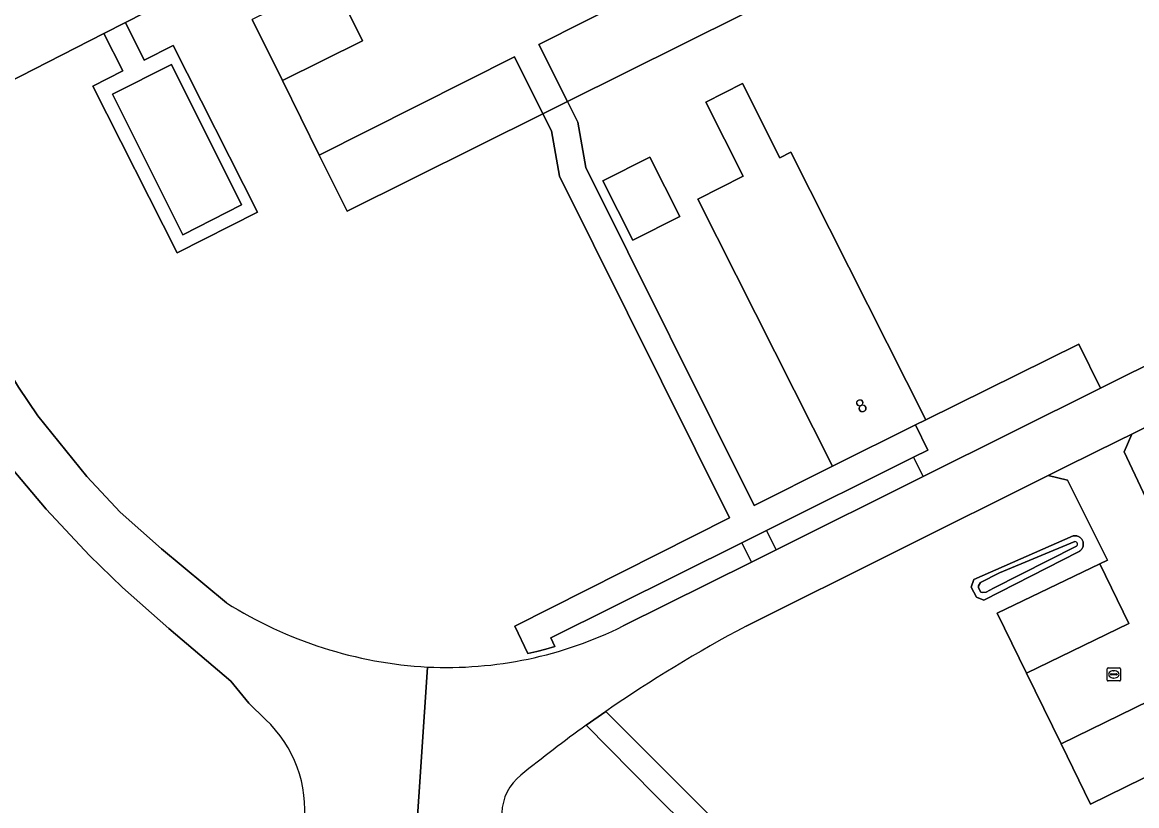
# Model space of a CAD drawing. Extents: x 158132 to 159664, y 385256 to 387218.
# Drawn here: x 159064.7 to 159149, y 386274.9 to 386334.2 of the extents above; entities that cross this region are included whole.
import ezdxf

# ---------------------------------------------------------------- set-up
doc = ezdxf.new("R2010")
doc.units = 0
for name, color, linetype in [('IMGEO_Berm_groen', 7, 'Continuous'), ('IMGEO_Groenvoorziening', 7, 'Continuous'), ('IMGEO_Kolk', 7, 'Continuous'), ('IMGEO_Loofbos', 7, 'Continuous'), ('IMGEO_Oever', 7, 'Continuous'), ('IMGEO_Pand', 7, 'Continuous'), ('IMGEO_Pand_nummerreeks', 7, 'Continuous'), ('IMGEO_Parkeervlak_halfverhard', 7, 'Continuous'), ('IMGEO_Parkeervlak_open', 7, 'Continuous'), ('IMGEO_Rijbaan_lokaal_gesloten', 7, 'Continuous'), ('IMGEO_Rijbaan_lokaal_open', 7, 'Continuous'), ('IMGEO_Voetpad_open', 7, 'Continuous'), ('IMGEO_Waterloop', 7, 'Continuous')]:
    doc.layers.add(name, color=color, linetype=linetype)

msp = doc.modelspace()

# ---------------------------------------------------------------- linework, layer by layer
at = {"layer": 'IMGEO_Berm_groen'}
msp.add_lwpolyline([(159137.109, 386251.107), (159129.699, 386258.673), (159120.184, 386268.183), (159112.56, 386275.748), (159107.364, 386281.01)], dxfattribs=at)
for centre, radius, start, end in [((159167.991, 386196.497), 104.01, 125.6545, 129.08043), ((159104.761, 386274.249), 3.794, 128.06163, 228.1555)]:
    msp.add_arc(centre, radius, start, end, dxfattribs=at)
at = {"layer": 'IMGEO_Groenvoorziening'}
for points in [[(159158.608, 386354.428), (159105.953, 386328.242), (159106.738, 386326.663), (159107.337, 386323.246), (159120.07, 386297.644), (159126.002, 386300.637), (159115.808, 386320.841), (159119.244, 386322.574), (159116.412, 386328.188), (159119.201, 386329.595), (159122.033, 386323.981), (159122.863, 386324.4), (159133.085, 386304.138), (159144.653, 386309.856), (159146.313, 386306.52), (159187.744, 386327.14)], [(159085.768, 386341.008), (159072.465, 386334.219), (159073.901, 386331.373), (159076.083, 386332.475), (159082.461, 386319.846), (159076.384, 386316.777), (159070.007, 386329.407), (159072.281, 386330.555), (159070.847, 386333.393), (159061.295, 386328.518)], [(159119.874, 386293.362), (159119.145, 386294.827), (159104.695, 386287.635), (159104.996, 386286.96), (159104.313, 386286.771), (159103.626, 386286.599), (159102.935, 386286.444), (159101.95, 386288.501), (159118.21, 386296.706), (159105.338, 386322.589), (159104.739, 386326.006), (159104.088, 386327.315), (159089.251, 386319.936), (159087.154, 386324.178), (159084.365, 386329.818), (159082.079, 386334.443)], [(159186.019, 386321.678), (159148.667, 386303.059), (159148.09, 386301.717), (159150.98, 386295.609)], [(159057.062, 386320.945), (159063.133, 386308.664), (159064.373, 386306.618), (159065.843, 386304.447), (159069.55, 386299.848), (159072.072, 386297.131), (159075.195, 386294.366), (159080.133, 386290.273)], [(159108.848, 386282.056), (159117.567, 386273.343), (159130.648, 386260.403), (159140.343, 386250.704), (159148.101, 386242.94), (159161.049, 386260.864), (159173.188, 386277.68), (159184.907, 386293.934), (159196.39, 386309.759)], [(159166.651, 386285.382), (159145.544, 386275.043), (159143.317, 386279.598), (159140.694, 386284.963), (159138.479, 386289.495), (159146.258, 386293.231), (159146.826, 386293.504), (159143.804, 386299.576), (159142.345, 386299.908), (159119.464, 386288.503)], [(159110.158, 386288.526), (159119.874, 386293.362)]]:
    msp.add_lwpolyline(points, dxfattribs=at)
for points in [[(159114.449, 386319.54), (159110.896, 386317.747), (159108.63, 386322.237), (159112.184, 386324.031)], [(159132.873, 386299.831), (159132.148, 386301.298), (159121.01, 386295.755), (159121.739, 386294.29)], [(159144.636, 386294.139), (159137.467, 386290.481), (159136.925, 386290.7), (159136.523, 386291.463), (159136.707, 386292.056), (159144.244, 386295.351), (159144.3, 386295.359), (159144.356, 386295.362), (159144.412, 386295.36), (159144.468, 386295.354), (159144.523, 386295.342), (159144.576, 386295.326), (159144.628, 386295.305), (159144.678, 386295.279), (159144.726, 386295.249), (159144.771, 386295.215), (159144.812, 386295.178), (159144.851, 386295.137), (159144.885, 386295.093), (159144.916, 386295.045), (159144.942, 386294.996), (159144.964, 386294.944), (159144.981, 386294.891), (159144.994, 386294.836), (159145.001, 386294.78), (159145.004, 386294.724), (159145.002, 386294.668), (159144.995, 386294.612), (159144.983, 386294.558), (159144.967, 386294.504), (159144.946, 386294.452), (159144.92, 386294.402), (159144.89, 386294.355), (159144.856, 386294.31), (159144.818, 386294.268), (159144.777, 386294.23), (159144.733, 386294.196), (159144.686, 386294.165)]]:
    msp.add_lwpolyline(points, close=True, dxfattribs=at)
for centre, radius, start, end in [((159097.116, 386317.23), 31.861, 237.78851, 266.82735), ((159096.795, 386315.367), 29.983, 267.2441, 296.46767), ((159168.468, 386195.847), 104.817, 117.87331, 124.66655)]:
    msp.add_arc(centre, radius, start, end, dxfattribs=at)
at = {"layer": 'IMGEO_Kolk'}
for p, q in [((159146.813, 386284.434), (159146.813, 386285.286)), ((159146.888, 386285.36), (159147.74, 386285.36)), ((159147.072, 386284.854), (159147.072, 386284.866)), ((159147.51, 386284.817), (159147.112, 386284.817)), ((159147.115, 386284.903), (159147.513, 386284.903)), ((159147.301, 386285.14), (159147.326, 386285.14)), ((159147.556, 386284.866), (159147.556, 386284.854)), ((159147.814, 386285.286), (159147.814, 386284.434)), ((159147.74, 386284.36), (159146.888, 386284.36)), ((159147.324, 386284.58), (159147.299, 386284.58))]:
    msp.add_line(p, q, dxfattribs=at)
for points in [[(159146.813, 386284.434), (159146.813, 386285.286)], [(159146.888, 386285.36), (159147.74, 386285.36)], [(159147.814, 386285.286), (159147.814, 386284.434)], [(159147.74, 386284.36), (159146.888, 386284.36)]]:
    msp.add_lwpolyline(points, dxfattribs=at)
for centre, radius, start, end in [((159146.89, 386285.284), 0.0765, 91.55205, 178.44795), ((159146.89, 386285.284), 0.0765, 91.55205, 178.44795), ((159147.112, 386284.863), 0.0403, 85.87752, 175.75265), ((159147.109, 386284.853), 0.0366, 178.93798, 274.71019), ((159147.513, 386284.86), 0.043, 264.86636, 352.45326), ((159147.517, 386284.865), 0.0386, 1.73085, 96.63898), ((159147.738, 386285.284), 0.0765, 1.55205, 88.44795), ((159147.738, 386285.284), 0.0765, 1.55205, 88.44795), ((159146.89, 386284.436), 0.0765, 181.55205, 268.44795), ((159146.89, 386284.436), 0.0765, 181.55205, 268.44795), ((159147.738, 386284.436), 0.0765, 271.55205, 358.44795), ((159147.738, 386284.436), 0.0765, 271.55205, 358.44795)]:
    msp.add_arc(centre, radius, start, end, dxfattribs=at)
for centre, major_axis, ratio, start_param, end_param in [((159147.3, 386284.86), (-0.387, 0.002), 0.722429, 4.712389, 7.853982), ((159147.325, 386284.86), (-0.39, 0.002), 0.717154, 1.570796, 4.712389)]:
    msp.add_ellipse(centre, major_axis=major_axis, ratio=ratio, start_param=start_param, end_param=end_param, dxfattribs=at)
at = {"layer": 'IMGEO_Loofbos'}
msp.add_lwpolyline([(159083.086, 386281.447), (159081.827, 386282.687), (159080.46, 386284.342), (159075.757, 386288.34), (159072.25, 386291.429), (159069.75, 386293.857), (159066.469, 386297.371), (159062.371, 386302.202), (159058.593, 386308.797), (159053.255, 386319.337)], dxfattribs=at)
msp.add_arc((159076.66, 386274.597), 9.393, 353.49158, 46.82994, dxfattribs=at)
at = {"layer": 'IMGEO_Oever'}
msp.add_lwpolyline([(159144.994, 386294.836), (159144.981, 386294.891), (159144.964, 386294.944), (159144.942, 386294.996), (159144.916, 386295.045), (159144.885, 386295.093), (159144.851, 386295.137), (159144.812, 386295.178), (159144.771, 386295.215), (159144.726, 386295.249), (159144.678, 386295.279), (159144.628, 386295.305), (159144.576, 386295.326), (159144.523, 386295.342), (159144.468, 386295.354), (159144.412, 386295.36), (159144.356, 386295.362), (159144.3, 386295.359), (159144.244, 386295.351), (159136.707, 386292.056), (159136.523, 386291.463), (159136.925, 386290.7), (159137.467, 386290.481), (159144.636, 386294.139), (159144.686, 386294.165), (159144.733, 386294.196), (159144.777, 386294.23), (159144.818, 386294.268), (159144.856, 386294.31), (159144.89, 386294.355), (159144.92, 386294.402), (159144.946, 386294.452), (159144.967, 386294.504), (159144.983, 386294.558), (159144.995, 386294.612), (159145.002, 386294.668), (159145.004, 386294.724), (159145.001, 386294.78)], close=True, dxfattribs=at)
msp.add_lwpolyline([(159144.432, 386294.536), (159138.209, 386291.377), (159137.637, 386291.076), (159137.369, 386291.056), (159137.251, 386291.092), (159137.074, 386291.422), (159137.074, 386291.572), (159137.227, 386291.818), (159138.657, 386292.539), (159144.359, 386294.915)], dxfattribs=at)
msp.add_arc((159144.36, 386294.719), 0.196, 291.40141, 90.40328, dxfattribs=at)
at = {"layer": 'IMGEO_Pand'}
for points in [[(159081.256, 386320.404), (159075.958, 386331.045), (159071.496, 386328.786), (159076.815, 386318.132)], [(159122.863, 386324.4), (159122.033, 386323.981), (159119.201, 386329.595), (159116.412, 386328.188), (159119.244, 386322.574), (159115.808, 386320.841), (159126.002, 386300.637), (159132.291, 386303.745), (159133.085, 386304.138)], [(159110.896, 386317.747), (159114.449, 386319.54), (159112.184, 386324.031), (159108.63, 386322.237)]]:
    msp.add_lwpolyline(points, close=True, dxfattribs=at)
at = {"layer": 'IMGEO_Parkeervlak_halfverhard'}
for points in [[(159158.608, 386354.428), (159156.297, 386359.015), (159103.78, 386332.554), (159105.953, 386328.242)], [(159088.141, 386337.458), (159082.079, 386334.443), (159084.365, 386329.818), (159090.434, 386332.819)], [(159104.088, 386327.315), (159101.92, 386331.617), (159087.154, 386324.178), (159089.251, 386319.936)]]:
    msp.add_lwpolyline(points, close=True, dxfattribs=at)
at = {"layer": 'IMGEO_Parkeervlak_open'}
for points in [[(159146.258, 386293.231), (159138.479, 386289.495), (159140.694, 386284.963), (159148.444, 386288.717)], [(159166.651, 386285.382), (159164.449, 386289.929), (159143.317, 386279.598), (159145.544, 386275.043)]]:
    msp.add_lwpolyline(points, close=True, dxfattribs=at)
at = {"layer": 'IMGEO_Rijbaan_lokaal_gesloten'}
for points in [[(159060.892, 386329.157), (159060.937, 386329.18), (159061.295, 386328.518), (159070.847, 386333.393), (159072.465, 386334.219), (159085.768, 386341.008), (159090.616, 386343.54), (159115.248, 386356.119), (159131.574, 386364.295), (159131.513, 386364.412), (159131.347, 386364.73), (159133.011, 386365.593)], [(159187.744, 386327.14), (159146.313, 386306.52), (159132.873, 386299.831), (159121.739, 386294.29), (159119.874, 386293.362), (159110.158, 386288.526)], [(159119.464, 386288.503), (159142.345, 386299.908), (159143.713, 386300.59), (159147.686, 386302.57), (159148.667, 386303.059), (159186.019, 386321.678)], [(159080.133, 386290.273), (159075.195, 386294.366), (159072.072, 386297.131), (159069.55, 386299.848), (159065.843, 386304.447), (159064.373, 386306.618), (159063.133, 386308.664), (159057.062, 386320.945), (159053.255, 386319.337), (159058.593, 386308.797), (159062.371, 386302.202), (159066.469, 386297.371), (159069.75, 386293.857), (159072.25, 386291.429), (159075.757, 386288.34), (159080.46, 386284.342), (159081.827, 386282.687), (159083.086, 386281.447)], [(159094.463, 386272.209), (159095.353, 386285.418)], [(159095.353, 386285.418), (159094.463, 386272.209)], [(159107.364, 386281.01), (159108.848, 386282.056)]]:
    msp.add_lwpolyline(points, dxfattribs=at)
msp.add_lwpolyline([(159132.148, 386301.298), (159133.233, 386301.839), (159132.291, 386303.745), (159126.002, 386300.637), (159120.07, 386297.644), (159107.337, 386323.246), (159106.738, 386326.663), (159105.953, 386328.242), (159104.088, 386327.315), (159104.739, 386326.006), (159105.338, 386322.589), (159118.21, 386296.706), (159101.95, 386288.501), (159102.935, 386286.444), (159103.626, 386286.599), (159104.313, 386286.771), (159104.996, 386286.96), (159104.695, 386287.635), (159119.145, 386294.827), (159121.01, 386295.755)], close=True, dxfattribs=at)
for centre, radius, start, end in [((159097.116, 386317.23), 31.861, 237.78851, 266.82735), ((159096.795, 386315.367), 29.983, 267.2441, 296.46767), ((159168.468, 386195.847), 104.817, 117.87331, 124.66655), ((159076.66, 386274.597), 9.393, 353.49158, 46.82994), ((159167.991, 386196.497), 104.01, 125.6545, 129.08043), ((159104.761, 386274.249), 3.794, 128.06163, 228.1555)]:
    msp.add_arc(centre, radius, start, end, dxfattribs=at)
at = {"layer": 'IMGEO_Rijbaan_lokaal_open'}
msp.add_lwpolyline([(159088.141, 386337.458), (159090.434, 386332.819), (159084.365, 386329.818), (159087.154, 386324.178), (159101.92, 386331.617), (159104.088, 386327.315), (159105.953, 386328.242), (159103.78, 386332.554), (159156.297, 386359.015)], dxfattribs=at)
msp.add_lwpolyline([(159164.449, 386289.929), (159161.883, 386295.226), (159154.152, 386291.482), (159151.929, 386296.073), (159150.98, 386295.609), (159148.09, 386301.717), (159148.667, 386303.059), (159147.686, 386302.57), (159143.713, 386300.59), (159142.345, 386299.908), (159143.804, 386299.576), (159146.826, 386293.504), (159146.258, 386293.231), (159148.444, 386288.717), (159140.694, 386284.963), (159143.317, 386279.598)], close=True, dxfattribs=at)
at = {"layer": 'IMGEO_Voetpad_open'}
for points in [[(159072.465, 386334.219), (159070.847, 386333.393), (159072.281, 386330.555), (159070.007, 386329.407), (159076.384, 386316.777), (159082.461, 386319.846), (159076.083, 386332.475), (159073.901, 386331.373)], [(159075.958, 386331.045), (159081.256, 386320.404), (159076.815, 386318.132), (159071.496, 386328.786)], [(159146.313, 386306.52), (159144.653, 386309.856), (159133.085, 386304.138), (159132.291, 386303.745), (159133.233, 386301.839), (159132.148, 386301.298), (159132.873, 386299.831)], [(159121.01, 386295.755), (159119.145, 386294.827), (159119.874, 386293.362), (159121.739, 386294.29)]]:
    msp.add_lwpolyline(points, close=True, dxfattribs=at)
msp.add_lwpolyline([(159161.049, 386260.864), (159148.101, 386242.94), (159140.343, 386250.704), (159130.648, 386260.403), (159117.567, 386273.343), (159108.848, 386282.056), (159107.364, 386281.01), (159112.56, 386275.748), (159120.184, 386268.183), (159129.699, 386258.673), (159137.109, 386251.107), (159146.983, 386241.291), (159140, 386233.33), (159141.561, 386231.755), (159148.321, 386239.967), (159163.035, 386224.02)], dxfattribs=at)
at = {"layer": 'IMGEO_Waterloop'}
msp.add_lwpolyline([(159144.359, 386294.915), (159138.657, 386292.539), (159137.227, 386291.818), (159137.074, 386291.572), (159137.074, 386291.422), (159137.251, 386291.092), (159137.369, 386291.056), (159137.637, 386291.076), (159138.209, 386291.377), (159144.432, 386294.536)], dxfattribs=at)
msp.add_arc((159144.36, 386294.719), 0.196, 291.40141, 90.40328, dxfattribs=at)

# ---------------------------------------------------------------- texts
at = {"layer": 'IMGEO_Pand_nummerreeks'}
msp.add_text('8', height=1, rotation=26.57951, dxfattribs=at).set_placement((159128.08, 386304.584))

doc.saveas('drawing.dxf')
